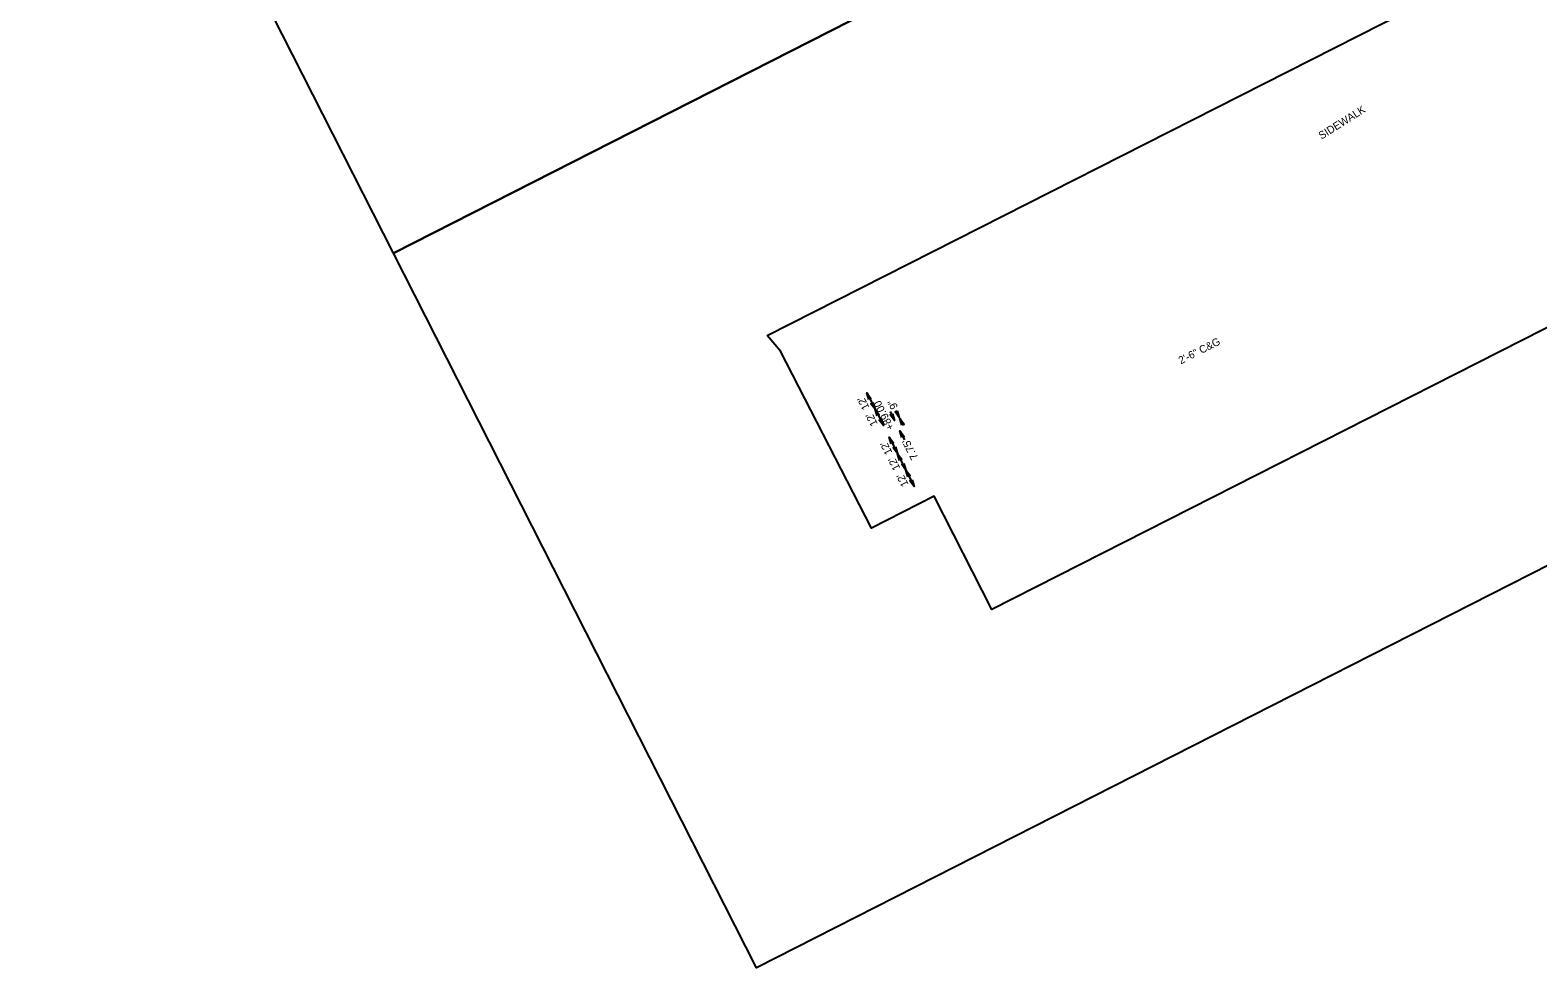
# Model space of a CAD drawing. Extents: x 2331355 to 2333079, y 611262 to 612828.
# Drawn here: x 2331355 to 2332342, y 611262 to 611876 of the extents above; entities that cross this region are included whole.
import ezdxf

# ---------------------------------------------------------------- set-up
doc = ezdxf.new("R2010")
doc.units = 0
for name, color, linetype in [('Old_Level_2', 7, 'Continuous'), ('Scratch_Level_1', 7, 'Continuous'), ('Sheet Plan CELL', 7, 'Continuous')]:
    doc.layers.add(name, color=color, linetype=linetype)

msp = doc.modelspace()

# ---------------------------------------------------------------- linework, layer by layer
at = {"layer": 'Old_Level_2'}
for p, q in [((2331902.79, 611638.57), (2331908.23, 611627.87)), ((2331908.23, 611627.87), (2331913.68, 611617.18)), ((2331918.06, 611626.42), (2331921.01, 611620.63)), ((2331921.78, 611627.18), (2331924.15, 611622.51)), ((2331924.49, 611621.84), (2331926.87, 611617.18)), ((2331924.52, 611613.72), (2331927.47, 611607.93)), ((2331917.5, 611609.62), (2331922.94, 611598.92)), ((2331923.01, 611598.79), (2331928.46, 611588.1)), ((2331928.46, 611588.1), (2331933.9, 611577.41))]:
    msp.add_line(p, q, dxfattribs=at)
for points in [[(2331904.14, 611634.2), (2331902.79, 611638.57), (2331905.55, 611634.9), (2331904.58, 611635.05)], [(2331906.88, 611632.23), (2331908.23, 611627.87), (2331905.47, 611631.54), (2331906.44, 611631.39)], [(2331909.58, 611623.51), (2331908.23, 611627.87), (2331911, 611624.2), (2331910.02, 611624.35)], [(2331912.33, 611621.54), (2331913.68, 611617.18), (2331910.91, 611620.85), (2331911.88, 611620.7)], [(2331919.66, 611624.99), (2331921.01, 611620.63), (2331918.24, 611624.3), (2331919.22, 611624.15)], [(2331922.8, 611626.87), (2331924.15, 611622.51), (2331921.38, 611626.18), (2331922.36, 611626.03)], [(2331925.84, 611617.48), (2331924.49, 611621.84), (2331927.26, 611618.17), (2331926.28, 611618.32)], [(2331925.87, 611609.36), (2331924.52, 611613.72), (2331927.29, 611610.05), (2331926.32, 611610.2)], [(2331918.85, 611605.26), (2331917.5, 611609.62), (2331920.27, 611605.95), (2331919.29, 611606.1)], [(2331921.59, 611603.29), (2331922.94, 611598.92), (2331920.18, 611602.59), (2331921.15, 611602.44)], [(2331924.36, 611594.43), (2331923.01, 611598.79), (2331925.78, 611595.12), (2331924.8, 611595.27)], [(2331927.1, 611592.46), (2331928.46, 611588.1), (2331925.69, 611591.77), (2331926.66, 611591.62)], [(2331929.81, 611583.74), (2331928.46, 611588.1), (2331931.22, 611584.43), (2331930.25, 611584.58)], [(2331932.55, 611581.77), (2331933.9, 611577.41), (2331931.13, 611581.07), (2331932.11, 611580.93)]]:
    msp.add_lwpolyline(points, close=True, dxfattribs=at)
at = {"layer": 'Scratch_Level_1'}
msp.add_lwpolyline([(2331837.64, 611676.12), (2332704.77, 612115.95), (2332809.39, 611915.29), (2331984.65, 611496.71), (2331946.94, 611570.91), (2331905.9, 611550.04), (2331846.41, 611665.97)], close=True, dxfattribs=at)
at = {"layer": 'Sheet Plan CELL'}
for points in [[(2331354.84, 612198.14), (2332231.99, 612644.09), (2332248.84, 612610.95), (2332379.58, 612677.42), (2332421.89, 612594.18), (2332493.28, 612630.48), (2332529.96, 612558.33), (2332698.67, 612644.11), (2332840.79, 612364.62), (2331592.76, 611730.15)], [(2331592.76, 611730.15), (2332840.78, 612364.62), (2333078.69, 611896.65), (2331830.66, 611262.19)]]:
    msp.add_lwpolyline(points, close=True, dxfattribs=at)

# ---------------------------------------------------------------- texts
at = {"layer": 'Old_Level_2'}
for s, rotation, p in [('SIDEWALK', 32.2313, (2332200.71, 611804.4)), ('2\'-6" C&G', 26.97858, (2332108.51, 611657.23)), ("12'", 116.97858, (2331904.73, 611629.01)), ('+89.00', 116.97858, (2331920.93, 611615.77)), ('9"', 116.97858, (2331923.4, 611629.42)), ("12'", 116.97858, (2331910.17, 611618.31)), ("12'", 116.97858, (2331919.67, 611599.66)), ("7.75'", 116.97858, (2331936.62, 611596.31)), ("12'", 116.97858, (2331924.92, 611589.35)), ("12'", 116.97858, (2331930.36, 611578.66))]:
    msp.add_text(s, height=5, rotation=rotation, dxfattribs=at).set_placement(p)

doc.saveas('drawing.dxf')
